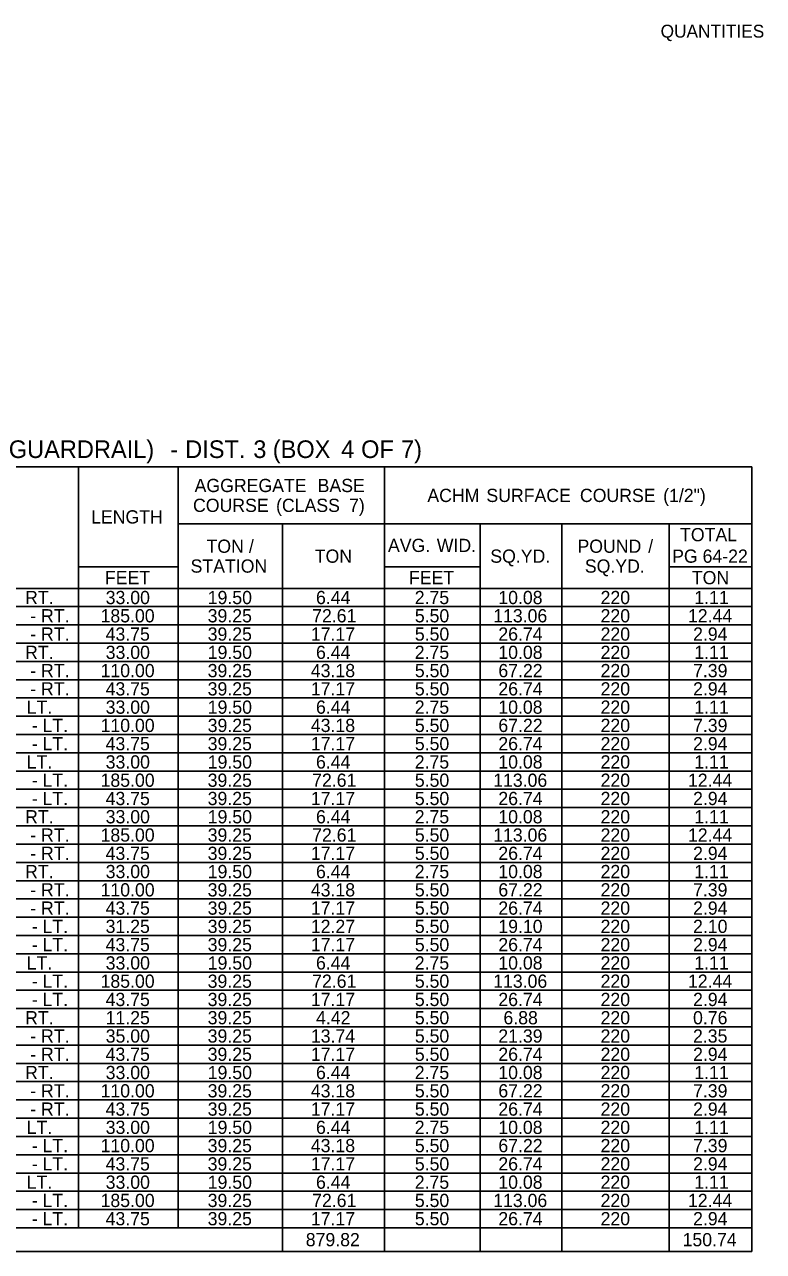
# Model space of a CAD drawing. Extents: x 544250 to 1930787, y -1948365 to 596640.
# Drawn here: x 558675 to 559010, y -1946614 to -1946058 of the extents above; entities that cross this region are included whole.
import ezdxf

# ---------------------------------------------------------------- set-up
doc = ezdxf.new("R2010")
doc.units = 0
doc.layers.add('Default', color=7, linetype='Continuous')
doc.layers.add('R_Border Prem', color=7, linetype='Continuous')

msp = doc.modelspace()

# ---------------------------------------------------------------- linework, layer by layer
at = {"layer": 'Default'}
for p, q in [((558321.63, -1946258.62), (559004.62, -1946258.62)), ((558698.95, -1946603.77), (558698.95, -1946258.62)), ((558744.29, -1946603.77), (558744.29, -1946258.62)), ((558837.89, -1946614.5), (558837.89, -1946258.62)), ((559004.62, -1946614.5), (559004.62, -1946258.62)), ((558744.29, -1946284.46), (559004.62, -1946284.46)), ((558791.58, -1946614.5), (558791.58, -1946284.46)), ((558881.28, -1946284.46), (558918.33, -1946284.46)), ((558881.28, -1946614.5), (558881.28, -1946284.46)), ((558918.33, -1946614.5), (558918.33, -1946284.46)), ((558967.08, -1946614.5), (558967.08, -1946284.46)), ((558698.95, -1946303.96), (558744.29, -1946303.96)), ((558744.29, -1946313.71), (558744.29, -1946303.96)), ((558837.89, -1946303.96), (558881.28, -1946303.96)), ((558837.89, -1946313.71), (558837.89, -1946303.96)), ((558881.28, -1946313.71), (558881.28, -1946303.96)), ((558967.08, -1946303.96), (559004.62, -1946303.96)), ((558321.63, -1946313.71), (559004.62, -1946313.71)), ((558744.29, -1946313.71), (558881.28, -1946313.71)), ((558881.28, -1946313.71), (559004.62, -1946313.71)), ((558527.84, -1946322), (559004.62, -1946322)), ((558527.84, -1946330.29), (559004.62, -1946330.29)), ((558527.84, -1946338.57), (559004.62, -1946338.57)), ((558527.84, -1946346.86), (559004.62, -1946346.86)), ((558527.84, -1946355.15), (559004.62, -1946355.15)), ((558527.84, -1946363.44), (559004.62, -1946363.44)), ((558527.84, -1946371.72), (559004.62, -1946371.72)), ((558527.84, -1946380.01), (559004.62, -1946380.01)), ((558527.84, -1946388.3), (559004.62, -1946388.3)), ((558527.84, -1946396.59), (559004.62, -1946396.59)), ((558527.84, -1946404.87), (559004.62, -1946404.87)), ((558321.63, -1946413.16), (559004.62, -1946413.16)), ((558527.84, -1946421.45), (559004.62, -1946421.45)), ((558527.84, -1946429.74), (559004.62, -1946429.74)), ((558527.84, -1946438.02), (559004.62, -1946438.02)), ((558527.84, -1946446.31), (559004.62, -1946446.31)), ((558527.84, -1946454.6), (559004.62, -1946454.6)), ((558527.84, -1946462.89), (559004.62, -1946462.89)), ((558527.84, -1946471.17), (559004.62, -1946471.17)), ((558527.84, -1946479.46), (559004.62, -1946479.46)), ((558527.84, -1946487.75), (559004.62, -1946487.75)), ((558527.84, -1946496.04), (559004.62, -1946496.04)), ((558321.63, -1946504.32), (559004.62, -1946504.32)), ((558527.84, -1946512.61), (559004.62, -1946512.61)), ((558527.84, -1946520.9), (559004.62, -1946520.9)), ((558527.84, -1946529.19), (559004.62, -1946529.19)), ((558527.84, -1946537.47), (559004.62, -1946537.47)), ((558527.84, -1946545.76), (559004.62, -1946545.76)), ((558527.84, -1946554.05), (559004.62, -1946554.05)), ((558527.84, -1946562.34), (559004.62, -1946562.34)), ((558527.84, -1946570.62), (559004.62, -1946570.62)), ((558527.84, -1946578.91), (559004.62, -1946578.91)), ((558527.84, -1946587.2), (559004.62, -1946587.2)), ((558527.84, -1946595.49), (559004.62, -1946595.49)), ((558321.63, -1946603.77), (559004.62, -1946603.77)), ((558791.58, -1946614.5), (558791.58, -1946603.77)), ((558881.28, -1946614.5), (558881.28, -1946603.77)), ((558918.33, -1946614.5), (558918.33, -1946603.77)), ((558967.08, -1946614.5), (558967.08, -1946603.77)), ((558321.63, -1946614.5), (559004.62, -1946614.5))]:
    msp.add_line(p, q, dxfattribs=at)

# ---------------------------------------------------------------- texts
for s, height, p in [(' GUARDRAIL)', 8, (558664.39, -1946254.58)), (' DIST.', 8, (558744.45, -1946254.58)), (' 3', 8, (558775.35, -1946254.58)), (' (BOX', 8, (558784.18, -1946254.58)), (' 4', 8, (558815.22, -1946254.58)), (' OF', 8, (558824.28, -1946254.58)), (' 7)', 8, (558842.39, -1946254.58)), (' -', 8, (558737.7, -1946254.58)), ('AGGREGATE', 6, (558751.68, -1946270.04)), (' BASE', 6, (558805.3, -1946270.04)), ('ACHM', 6, (558857.32, -1946274.54)), (' SURFACE', 6, (558881.87, -1946274.54)), (' COURSE', 6, (558924.31, -1946274.54)), (' (1/2")', 6, (558962.09, -1946274.54)), ('COURSE', 6, (558750.97, -1946279.04)), (' (CLASS', 6, (558786.42, -1946279.04)), (' 7)', 6, (558819.55, -1946279.04)), ('LENGTH', 6, (558704.71, -1946284.29)), ('TOTAL', 6, (558972, -1946292.34)), ('TON', 6, (558757.09, -1946297.59)), (' /', 6, (558774.12, -1946297.59)), ('AVG.', 6, (558839.44, -1946297.21)), (' WID.', 6, (558859.36, -1946297.21)), ('POUND', 6, (558925.44, -1946297.59)), (' /', 6, (558955.3, -1946297.59)), ('TON', 6, (558806.22, -1946302.09)), ('SQ.YD.', 6, (558885.88, -1946302.09)), ('PG', 6, (558968.38, -1946302.09)), (' 64-22', 6, (558979.98, -1946302.09)), ('STATION', 6, (558749.87, -1946306.59)), ('SQ.YD.', 6, (558928.78, -1946306.59)), ('FEET', 6, (558710.99, -1946311.84)), ('FEET', 6, (558848.96, -1946311.84)), ('TON', 6, (558977.33, -1946311.84)), (' RT.', 6, (558672.53, -1946320.86)), ('33.00', 6, (558711.34, -1946320.86)), ('19.50', 6, (558757.65, -1946320.86)), ('6.44', 6, (558806.78, -1946320.86)), ('2.75', 6, (558851.6, -1946320.86)), ('10.08', 6, (558889.51, -1946320.86)), ('220', 6, (558935.92, -1946320.86)), ('1.11', 6, (558978.46, -1946320.86)), (' -', 6, (558674.91, -1946329.14)), (' RT.', 6, (558679.77, -1946329.14)), ('185.00', 6, (558709.01, -1946329.14)), ('39.25', 6, (558757.62, -1946329.14)), ('72.61', 6, (558805.02, -1946329.14)), ('5.50', 6, (558851.63, -1946329.14)), ('113.06', 6, (558887.18, -1946329.14)), ('220', 6, (558935.92, -1946329.14)), ('12.44', 6, (558975.57, -1946329.14)), (' RT.', 6, (558679.77, -1946337.43)), ('43.75', 6, (558711.31, -1946337.43)), ('39.25', 6, (558757.62, -1946337.43)), ('17.17', 6, (558804.44, -1946337.43)), ('5.50', 6, (558851.63, -1946337.43)), ('26.74', 6, (558889.52, -1946337.43)), ('220', 6, (558935.92, -1946337.43)), ('2.94', 6, (558977.9, -1946337.43)), (' -', 6, (558674.91, -1946337.43)), (' RT.', 6, (558672.53, -1946345.72)), ('33.00', 6, (558711.34, -1946345.72)), ('19.50', 6, (558757.65, -1946345.72)), ('6.44', 6, (558806.78, -1946345.72)), ('2.75', 6, (558851.6, -1946345.72)), ('10.08', 6, (558889.51, -1946345.72)), ('220', 6, (558935.92, -1946345.72)), ('1.11', 6, (558978.46, -1946345.72)), (' RT.', 6, (558679.77, -1946354.01)), ('110.00', 6, (558709.01, -1946354.01)), ('39.25', 6, (558757.62, -1946354.01)), ('43.18', 6, (558804.44, -1946354.01)), ('5.50', 6, (558851.63, -1946354.01)), ('67.22', 6, (558889.54, -1946354.01)), ('220', 6, (558935.92, -1946354.01)), ('7.39', 6, (558977.88, -1946354.01)), (' -', 6, (558674.91, -1946354.01)), (' -', 6, (558674.91, -1946362.29)), (' RT.', 6, (558679.77, -1946362.29)), ('43.75', 6, (558711.31, -1946362.29)), ('39.25', 6, (558757.62, -1946362.29)), ('17.17', 6, (558804.44, -1946362.29)), ('5.50', 6, (558851.63, -1946362.29)), ('26.74', 6, (558889.52, -1946362.29)), ('220', 6, (558935.92, -1946362.29)), ('2.94', 6, (558977.9, -1946362.29)), (' LT.', 6, (558673.23, -1946370.58)), ('33.00', 6, (558711.34, -1946370.58)), ('19.50', 6, (558757.65, -1946370.58)), ('6.44', 6, (558806.78, -1946370.58)), ('2.75', 6, (558851.6, -1946370.58)), ('10.08', 6, (558889.51, -1946370.58)), ('220', 6, (558935.92, -1946370.58)), ('1.11', 6, (558978.46, -1946370.58)), (' -', 6, (558675.61, -1946378.87)), (' LT.', 6, (558680.47, -1946378.87)), ('110.00', 6, (558709.01, -1946378.87)), ('39.25', 6, (558757.62, -1946378.87)), ('43.18', 6, (558804.44, -1946378.87)), ('5.50', 6, (558851.63, -1946378.87)), ('67.22', 6, (558889.54, -1946378.87)), ('220', 6, (558935.92, -1946378.87)), ('7.39', 6, (558977.88, -1946378.87)), (' LT.', 6, (558680.47, -1946387.16)), ('43.75', 6, (558711.31, -1946387.16)), ('39.25', 6, (558757.62, -1946387.16)), ('17.17', 6, (558804.44, -1946387.16)), ('5.50', 6, (558851.63, -1946387.16)), ('26.74', 6, (558889.52, -1946387.16)), ('220', 6, (558935.92, -1946387.16)), ('2.94', 6, (558977.9, -1946387.16)), (' -', 6, (558675.61, -1946387.16)), (' LT.', 6, (558673.23, -1946395.44)), ('33.00', 6, (558711.34, -1946395.44)), ('19.50', 6, (558757.65, -1946395.44)), ('6.44', 6, (558806.78, -1946395.44)), ('2.75', 6, (558851.6, -1946395.44)), ('10.08', 6, (558889.51, -1946395.44)), ('220', 6, (558935.92, -1946395.44)), ('1.11', 6, (558978.46, -1946395.44)), (' LT.', 6, (558680.47, -1946403.73)), ('185.00', 6, (558709.01, -1946403.73)), ('39.25', 6, (558757.62, -1946403.73)), ('72.61', 6, (558805.02, -1946403.73)), ('5.50', 6, (558851.63, -1946403.73)), ('113.06', 6, (558887.18, -1946403.73)), ('220', 6, (558935.92, -1946403.73)), ('12.44', 6, (558975.57, -1946403.73)), (' -', 6, (558675.61, -1946403.73)), (' -', 6, (558675.61, -1946412.02)), (' LT.', 6, (558680.47, -1946412.02)), ('43.75', 6, (558711.31, -1946412.02)), ('39.25', 6, (558757.62, -1946412.02)), ('17.17', 6, (558804.44, -1946412.02)), ('5.50', 6, (558851.63, -1946412.02)), ('26.74', 6, (558889.52, -1946412.02)), ('220', 6, (558935.92, -1946412.02)), ('2.94', 6, (558977.9, -1946412.02)), (' RT.', 6, (558672.53, -1946420.31)), ('33.00', 6, (558711.34, -1946420.31)), ('19.50', 6, (558757.65, -1946420.31)), ('6.44', 6, (558806.78, -1946420.31)), ('2.75', 6, (558851.6, -1946420.31)), ('10.08', 6, (558889.51, -1946420.31)), ('220', 6, (558935.92, -1946420.31)), ('1.11', 6, (558978.46, -1946420.31)), (' -', 6, (558674.91, -1946428.59)), (' RT.', 6, (558679.77, -1946428.59)), ('185.00', 6, (558709.01, -1946428.59)), ('39.25', 6, (558757.62, -1946428.59)), ('72.61', 6, (558805.02, -1946428.59)), ('5.50', 6, (558851.63, -1946428.59)), ('113.06', 6, (558887.18, -1946428.59)), ('220', 6, (558935.92, -1946428.59)), ('12.44', 6, (558975.57, -1946428.59)), (' RT.', 6, (558679.77, -1946436.88)), ('43.75', 6, (558711.31, -1946436.88)), ('39.25', 6, (558757.62, -1946436.88)), ('17.17', 6, (558804.44, -1946436.88)), ('5.50', 6, (558851.63, -1946436.88)), ('26.74', 6, (558889.52, -1946436.88)), ('220', 6, (558935.92, -1946436.88)), ('2.94', 6, (558977.9, -1946436.88)), (' -', 6, (558674.91, -1946436.88)), (' RT.', 6, (558672.53, -1946445.17)), ('33.00', 6, (558711.34, -1946445.17)), ('19.50', 6, (558757.65, -1946445.17)), ('6.44', 6, (558806.78, -1946445.17)), ('2.75', 6, (558851.6, -1946445.17)), ('10.08', 6, (558889.51, -1946445.17)), ('220', 6, (558935.92, -1946445.17)), ('1.11', 6, (558978.46, -1946445.17)), (' RT.', 6, (558679.77, -1946453.46)), ('110.00', 6, (558709.01, -1946453.46)), ('39.25', 6, (558757.62, -1946453.46)), ('43.18', 6, (558804.44, -1946453.46)), ('5.50', 6, (558851.63, -1946453.46)), ('67.22', 6, (558889.54, -1946453.46)), ('220', 6, (558935.92, -1946453.46)), ('7.39', 6, (558977.88, -1946453.46)), (' -', 6, (558674.91, -1946453.46)), (' -', 6, (558674.91, -1946461.74)), (' RT.', 6, (558679.77, -1946461.74)), ('43.75', 6, (558711.31, -1946461.74)), ('39.25', 6, (558757.62, -1946461.74)), ('17.17', 6, (558804.44, -1946461.74)), ('5.50', 6, (558851.63, -1946461.74)), ('26.74', 6, (558889.52, -1946461.74)), ('220', 6, (558935.92, -1946461.74)), ('2.94', 6, (558977.9, -1946461.74)), (' LT.', 6, (558680.47, -1946470.03)), ('31.25', 6, (558711.31, -1946470.03)), ('39.25', 6, (558757.62, -1946470.03)), ('12.27', 6, (558804.44, -1946470.03)), ('5.50', 6, (558851.63, -1946470.03)), ('19.10', 6, (558889.52, -1946470.03)), ('220', 6, (558935.92, -1946470.03)), ('2.10', 6, (558977.89, -1946470.03)), (' -', 6, (558675.61, -1946470.03)), (' -', 6, (558675.61, -1946478.32)), (' LT.', 6, (558680.47, -1946478.32)), ('43.75', 6, (558711.31, -1946478.32)), ('39.25', 6, (558757.62, -1946478.32)), ('17.17', 6, (558804.44, -1946478.32)), ('5.50', 6, (558851.63, -1946478.32)), ('26.74', 6, (558889.52, -1946478.32)), ('220', 6, (558935.92, -1946478.32)), ('2.94', 6, (558977.9, -1946478.32)), (' LT.', 6, (558673.23, -1946486.61)), ('33.00', 6, (558711.34, -1946486.61)), ('19.50', 6, (558757.65, -1946486.61)), ('6.44', 6, (558806.78, -1946486.61)), ('2.75', 6, (558851.6, -1946486.61)), ('10.08', 6, (558889.51, -1946486.61)), ('220', 6, (558935.92, -1946486.61)), ('1.11', 6, (558978.46, -1946486.61)), (' -', 6, (558675.61, -1946494.89)), (' LT.', 6, (558680.47, -1946494.89)), ('185.00', 6, (558709.01, -1946494.89)), ('39.25', 6, (558757.62, -1946494.89)), ('72.61', 6, (558805.02, -1946494.89)), ('5.50', 6, (558851.63, -1946494.89)), ('113.06', 6, (558887.18, -1946494.89)), ('220', 6, (558935.92, -1946494.89)), ('12.44', 6, (558975.57, -1946494.89)), (' LT.', 6, (558680.47, -1946503.18)), ('43.75', 6, (558711.31, -1946503.18)), ('39.25', 6, (558757.62, -1946503.18)), ('17.17', 6, (558804.44, -1946503.18)), ('5.50', 6, (558851.63, -1946503.18)), ('26.74', 6, (558889.52, -1946503.18)), ('220', 6, (558935.92, -1946503.18)), ('2.94', 6, (558977.9, -1946503.18)), (' -', 6, (558675.61, -1946503.18)), (' RT.', 6, (558672.53, -1946511.47)), ('11.25', 6, (558711.31, -1946511.47)), ('39.25', 6, (558757.62, -1946511.47)), ('4.42', 6, (558806.8, -1946511.47)), ('5.50', 6, (558851.63, -1946511.47)), ('6.88', 6, (558891.84, -1946511.47)), ('220', 6, (558935.92, -1946511.47)), ('0.76', 6, (558977.88, -1946511.47)), (' RT.', 6, (558679.77, -1946519.76)), ('35.00', 6, (558711.34, -1946519.76)), ('39.25', 6, (558757.62, -1946519.76)), ('13.74', 6, (558804.45, -1946519.76)), ('5.50', 6, (558851.63, -1946519.76)), ('21.39', 6, (558889.51, -1946519.76)), ('220', 6, (558935.92, -1946519.76)), ('2.35', 6, (558977.86, -1946519.76)), (' -', 6, (558674.91, -1946519.76)), (' -', 6, (558674.91, -1946528.04)), (' RT.', 6, (558679.77, -1946528.04)), ('43.75', 6, (558711.31, -1946528.04)), ('39.25', 6, (558757.62, -1946528.04)), ('17.17', 6, (558804.44, -1946528.04)), ('5.50', 6, (558851.63, -1946528.04)), ('26.74', 6, (558889.52, -1946528.04)), ('220', 6, (558935.92, -1946528.04)), ('2.94', 6, (558977.9, -1946528.04)), (' RT.', 6, (558672.53, -1946536.33)), ('33.00', 6, (558711.34, -1946536.33)), ('19.50', 6, (558757.65, -1946536.33)), ('6.44', 6, (558806.78, -1946536.33)), ('2.75', 6, (558851.6, -1946536.33)), ('10.08', 6, (558889.51, -1946536.33)), ('220', 6, (558935.92, -1946536.33)), ('1.11', 6, (558978.46, -1946536.33)), (' -', 6, (558674.91, -1946544.62)), (' RT.', 6, (558679.77, -1946544.62)), ('110.00', 6, (558709.01, -1946544.62)), ('39.25', 6, (558757.62, -1946544.62)), ('43.18', 6, (558804.44, -1946544.62)), ('5.50', 6, (558851.63, -1946544.62)), ('67.22', 6, (558889.54, -1946544.62)), ('220', 6, (558935.92, -1946544.62)), ('7.39', 6, (558977.88, -1946544.62)), (' RT.', 6, (558679.77, -1946552.91)), ('43.75', 6, (558711.31, -1946552.91)), ('39.25', 6, (558757.62, -1946552.91)), ('17.17', 6, (558804.44, -1946552.91)), ('5.50', 6, (558851.63, -1946552.91)), ('26.74', 6, (558889.52, -1946552.91)), ('220', 6, (558935.92, -1946552.91)), ('2.94', 6, (558977.9, -1946552.91)), (' -', 6, (558674.91, -1946552.91)), ('33.00', 6, (558711.34, -1946561.19)), ('19.50', 6, (558757.65, -1946561.19)), ('6.44', 6, (558806.78, -1946561.19)), ('2.75', 6, (558851.6, -1946561.19)), ('10.08', 6, (558889.51, -1946561.19)), ('220', 6, (558935.92, -1946561.19)), (' LT.', 6, (558673.23, -1946561.19)), ('1.11', 6, (558978.46, -1946561.19)), (' LT.', 6, (558680.47, -1946569.48)), ('110.00', 6, (558709.01, -1946569.48)), ('39.25', 6, (558757.62, -1946569.48)), ('43.18', 6, (558804.44, -1946569.48)), ('5.50', 6, (558851.63, -1946569.48)), ('67.22', 6, (558889.54, -1946569.48)), ('220', 6, (558935.92, -1946569.48)), ('7.39', 6, (558977.88, -1946569.48)), (' -', 6, (558675.61, -1946569.48)), (' LT.', 6, (558680.47, -1946577.77)), ('43.75', 6, (558711.31, -1946577.77)), ('39.25', 6, (558757.62, -1946577.77)), ('17.17', 6, (558804.44, -1946577.77)), ('5.50', 6, (558851.63, -1946577.77)), ('26.74', 6, (558889.52, -1946577.77)), ('220', 6, (558935.92, -1946577.77)), ('2.94', 6, (558977.9, -1946577.77)), (' -', 6, (558675.61, -1946577.77)), (' LT.', 6, (558673.23, -1946586.06)), ('33.00', 6, (558711.34, -1946586.06)), ('19.50', 6, (558757.65, -1946586.06)), ('6.44', 6, (558806.78, -1946586.06)), ('2.75', 6, (558851.6, -1946586.06)), ('10.08', 6, (558889.51, -1946586.06)), ('220', 6, (558935.92, -1946586.06)), ('1.11', 6, (558978.46, -1946586.06)), (' LT.', 6, (558680.47, -1946594.34)), ('185.00', 6, (558709.01, -1946594.34)), ('39.25', 6, (558757.62, -1946594.34)), ('72.61', 6, (558805.02, -1946594.34)), ('5.50', 6, (558851.63, -1946594.34)), ('113.06', 6, (558887.18, -1946594.34)), ('220', 6, (558935.92, -1946594.34)), ('12.44', 6, (558975.57, -1946594.34)), (' -', 6, (558675.61, -1946594.34)), (' LT.', 6, (558680.47, -1946602.63)), ('43.75', 6, (558711.31, -1946602.63)), ('39.25', 6, (558757.62, -1946602.63)), ('17.17', 6, (558804.44, -1946602.63)), ('5.50', 6, (558851.63, -1946602.63)), ('26.74', 6, (558889.52, -1946602.63)), ('220', 6, (558935.92, -1946602.63)), ('2.94', 6, (558977.9, -1946602.63)), (' -', 6, (558675.61, -1946602.63)), ('879.82', 6, (558802.13, -1946612.14)), ('150.74', 6, (558973.13, -1946612.14))]:
    msp.add_text(s, height=height, dxfattribs=at).set_placement(p)
at = {"layer": 'R_Border Prem'}
msp.add_text('QUANTITIES', height=5.862, rotation=360, dxfattribs=at).set_placement((558963.16, -1946063.9))

doc.saveas('drawing.dxf')
